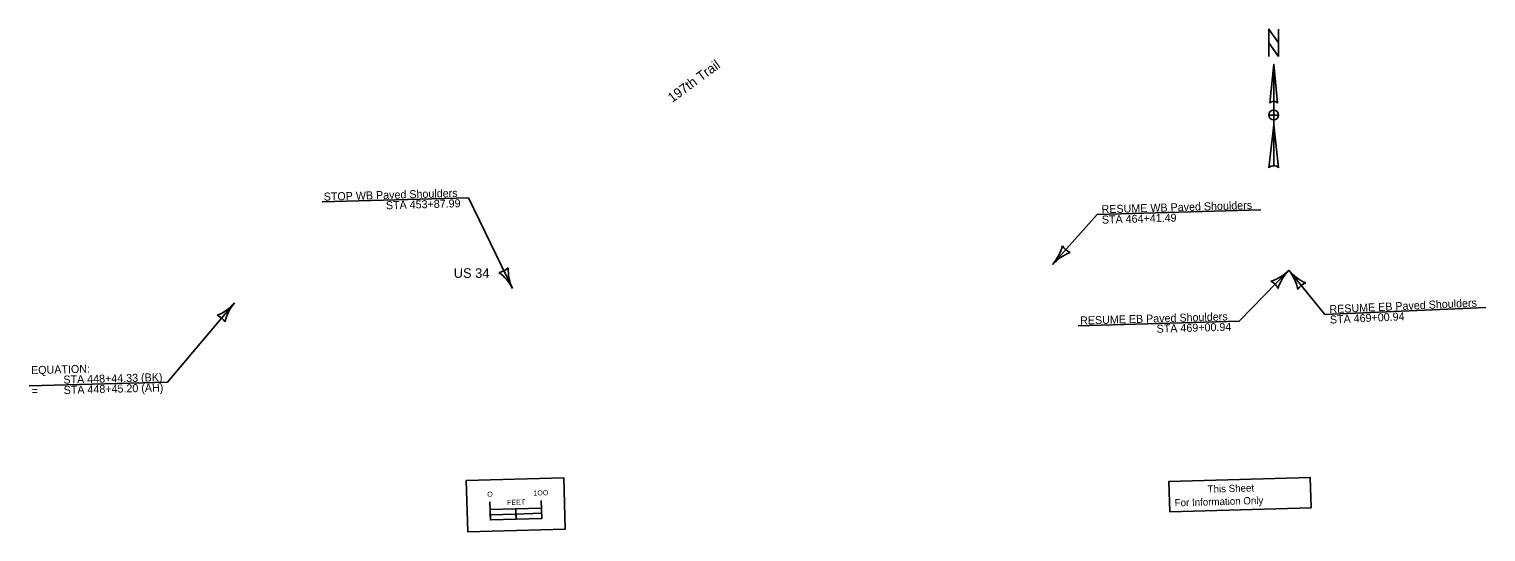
# Model space of a CAD drawing. Extents: x 22712865 to 22760106, y 6235088 to 6238602.
# Drawn here: x 22722123 to 22724962, y 6235347 to 6236326 of the extents above; entities that cross this region are included whole.
import ezdxf

# ---------------------------------------------------------------- set-up
doc = ezdxf.new("R2010")
doc.units = 0
for name, color, linetype in [('_CIVIL_CONSTRUCTION', 7, 'Continuous'), ('Contours Major', 7, 'Continuous'), ('Default', 7, 'Continuous'), ('Draft_3', 7, 'Continuous'), ('dsnTextOdd', 7, 'Continuous'), ('Entrance', 7, 'Continuous')]:
    doc.layers.add(name, color=color, linetype=linetype)

msp = doc.modelspace()

# ---------------------------------------------------------------- linework, layer by layer
at = {"layer": '_CIVIL_CONSTRUCTION'}
msp.add_line((22723071.9, 6235371.7), (22723071.3, 6235391.7), dxfattribs=at)
msp.add_line((22723071.9, 6235371.7), (22723071.3, 6235391.7), dxfattribs=at)
for points in [[(22722974.7, 6235447), (22723164.6, 6235452.4), (22723167.5, 6235352.4), (22722977.5, 6235347.1)], [(22722977.5, 6235347.1), (22722974.7, 6235447), (22723164.6, 6235452.4), (22723167.5, 6235352.4)], [(22723021.9, 6235370.3), (22723071.9, 6235371.7), (22723071.6, 6235381.8), (22723021.6, 6235380.4)], [(22723071.6, 6235381.8), (22723121.6, 6235383.2), (22723121.3, 6235393.1), (22723071.3, 6235391.7)]]:
    msp.add_lwpolyline(points, close=True, dxfattribs=at)
for points in [[(22723020.9, 6235405.3), (22723021.9, 6235370.3), (22723121.9, 6235373.1), (22723120.9, 6235408.1)], [(22723021.3, 6235390.3), (22723121.3, 6235393.1)]]:
    msp.add_lwpolyline(points, dxfattribs=at)
at = {"layer": 'Contours Major'}
msp.add_lwpolyline([(22722522.9, 6235793), (22722392.6, 6235638.7), (22722122.8, 6235631.6)], dxfattribs=at)
for centre, radius, start, end in [((22722458, 6235847.9), 85, 291.7468, 319.8193), ((22722587.8, 6235738.2), 85, 139.8193, 167.8918), ((22722476.9, 6235738.6), 32.8, 32.0859, 67.5526)]:
    msp.add_arc(centre, radius, start, end, dxfattribs=at)
at = {"layer": 'Draft_3'}
msp.add_lwpolyline([(22723064.9, 6235820.9), (22722978.8, 6235997.9), (22722693.9, 6235989.8)], dxfattribs=at)
for centre, radius, start, end in [((22723033.7, 6235885), 32.8, 278.2193, 313.686), ((22723141.4, 6235858.1), 85, 177.8801, 205.9526), ((22722988.5, 6235783.7), 85, 25.9526, 54.0251)]:
    msp.add_arc(centre, radius, start, end, dxfattribs=at)
at = {"layer": 'dsnTextOdd'}
msp.add_lwpolyline([(22724577.7, 6235856.8), (22724648.2, 6235770.2), (22724961.7, 6235784.4)], dxfattribs=at)
for centre, radius, start, end in [((22724511.8, 6235803.1), 85, 11.0911, 39.1636), ((22724643.6, 6235910.5), 85, 219.1636, 247.236), ((22724622.7, 6235801.6), 32.8, 111.4302, 146.8969)]:
    msp.add_arc(centre, radius, start, end, dxfattribs=at)
at = {"layer": 'Entrance'}
for p, q in [((22724548.3, 6236257.9), (22724555.9, 6236181.9)), ((22724548.3, 6236257.9), (22724548.3, 6236060.2)), ((22724540.7, 6236181.9), (22724540.7, 6236181.9)), ((22724541, 6236182.6), (22724542.4, 6236184.1)), ((22724548.3, 6236149.5), (22724548.3, 6236149.5)), ((22724538.8, 6236056.4), (22724548.3, 6236140))]:
    msp.add_line(p, q, dxfattribs=at)
for points in [[(22724557.8, 6236273.1), (22724538.8, 6236299.8), (22724538.8, 6236326.4), (22724557.8, 6236299.8)], [(22724345.6, 6235386.2), (22724621.1, 6235394), (22724619.5, 6235453.1), (22724344, 6235445.3)], [(22724344, 6235445.3), (22724619.5, 6235453.1), (22724621.1, 6235394), (22724345.6, 6235386.2)]]:
    msp.add_lwpolyline(points, close=True, dxfattribs=at)
for points in [[(22724538.8, 6236273.1), (22724538.8, 6236326.4), (22724557.8, 6236299.8), (22724557.8, 6236326.4)], [(22724540.7, 6236181.9), (22724548.3, 6236257.9), (22724548.3, 6236185.7)], [(22724548.3, 6236149.5), (22724548.3, 6236159), (22724538.8, 6236159)], [(22724557.8, 6236159), (22724548.3, 6236159), (22724548.3, 6236168.6)], [(22724548.3, 6236060.2), (22724548.3, 6236140), (22724557.8, 6236056.4)], [(22724117.3, 6235868), (22724204.1, 6235965), (22724523, 6235974.1)], [(22724577.7, 6235856.8), (22724480.7, 6235757.4), (22724167.4, 6235748.5)]]:
    msp.add_lwpolyline(points, dxfattribs=at)
for centre, radius, start, end in [((22724548.3, 6236176.2), 9.51, 90.0204, 143.1257), ((22724548.3, 6236176.2), 9.5, 36.8481, 90.0218), ((22724548.3, 6236159), 9.51, 90, 180), ((22724548.3, 6236159), 9.51, 180, 270), ((22724548.3, 6236159), 9.51, 0, 90), ((22724548.3, 6236159), 9.51, 270, 360), ((22724548.3, 6236046.4), 13.8, 89.9894, 133.619), ((22724548.3, 6236046.4), 13.8, 46.4021, 90.0006), ((22724053.9, 6235924.7), 85, 318.1735, 346.246), ((22724180.6, 6235811.3), 85, 110.101, 138.1735), ((22724164.8, 6235921.1), 32.8, 210.4401, 245.9068), ((22724516.8, 6235916.2), 85, 287.6566, 315.7291), ((22724527.9, 6235805.8), 32.8, 27.9958, 63.4625), ((22724638.6, 6235797.5), 85, 135.7291, 163.8016)]:
    msp.add_arc(centre, radius, start, end, dxfattribs=at)

# ---------------------------------------------------------------- texts
at = {"layer": '_CIVIL_CONSTRUCTION'}
for s, p in [('O', (22723015.7, 6235415.2)), ('O', (22723015.7, 6235415.2)), ('FEET', (22723054.2, 6235399.2)), ('1OO', (22723105.7, 6235417.7)), ('1OO', (22723105.7, 6235417.7))]:
    msp.add_text(s, height=10, rotation=1.6202, dxfattribs=at).set_placement(p)
at = {"layer": 'Contours Major'}
for s, height, p in [('EQUATION:', 15.6, (22722126.8, 6235654.2)), ('STA 448+44.33 (BK)', 15.601, (22722189.8, 6235635.7)), ('STA 448+45.20 (AH)', 15.601, (22722190.3, 6235615.5)), ('=', 15.6, (22722127.9, 6235613.8))]:
    msp.add_text(s, height=height, rotation=1.5081, dxfattribs=at).set_placement(p)
at = {"layer": 'Default'}
for s, rotation, p in [('197th Trail', 36.4595, (22723376.1, 6236182.4)), ('US 34', 359.6185, (22722950.2, 6235842))]:
    msp.add_text(s, height=18.75, rotation=rotation, dxfattribs=at).set_placement(p)
at = {"layer": 'Draft_3'}
for s, p in [('STOP WB Paved Shoulders', (22722697.1, 6235992.2)), ('STA 453+87.99', (22722818.3, 6235975.4))]:
    msp.add_text(s, height=15.601, rotation=1.6202, dxfattribs=at).set_placement(p)
at = {"layer": 'dsnTextOdd'}
for s, p in [('RESUME EB Paved Shoulders', (22724657.2, 6235772.9)), ('STA 469+00.94', (22724658.1, 6235752.7))]:
    msp.add_text(s, height=15.601, rotation=2.5911, dxfattribs=at).set_placement(p)
at = {"layer": 'Entrance'}
for s, height, p in [('RESUME WB Paved Shoulders', 15.601, (22724213.1, 6235967.6)), ('STA 464+41.49', 15.601, (22724213.6, 6235947.4)), ('RESUME EB Paved Shoulders', 15.601, (22724171.2, 6235750.9)), ('STA 469+00.94', 15.601, (22724320.3, 6235734.9)), ('This Sheet', 14.17, (22724419.7, 6235423.2)), ('For Information Only', 14.175, (22724355.5, 6235396.6))]:
    msp.add_text(s, height=height, rotation=1.6202, dxfattribs=at).set_placement(p)

doc.saveas('drawing.dxf')
